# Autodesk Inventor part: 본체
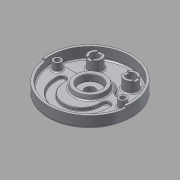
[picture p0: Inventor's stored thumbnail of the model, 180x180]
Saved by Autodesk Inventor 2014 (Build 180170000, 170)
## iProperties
Created: 2015-06
Part Number: 본체
Material: 알루미늄 6061
Document SubType Name: Modeling
Designer: MYHOME
Mass: 1070.54 g
Surface Area: 1035.57 cm^2
Volume: 395.033 cm^3
Density: 2.71 g/cm^3
Appearance: 알루미늄 - 평지
Author: MYHOME
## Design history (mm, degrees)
sketch "스케치1"
  geometry: C1 r 95 at (0, 0); 1 further point
  constraints: 1 centre point, 1 coincident
  dimensions: "d0" = 190 diameter of C1
extrude "돌출1" new body sketch "스케치1" distance "d1" = 32; taper "d2" = 0 deg
sketch "스케치3"
  geometry: L1 (-34.013, 24.639)-(-125.605, 24.639); L2 (34.013, 24.639)-(121.919, 24.639); C1 r 95 at (0, 0) reference; C2 r 90 at (0, 0); A1 r 42 centre (0, 0) between (-34.013, 24.639) and (34.013, 24.639)
  constraints: 4 end point, 2 centre point, 2 coincident, 2 point on circle, 1 collinear, 1 horizontal, 1 point on line
  dimensions: "d6" = 180 diameter of C2; "d125" = 84 diameter of A1; "d126" = 24.63947 distance from line of C1.centre L1
extrude "돌출3" cut sketch "스케치3" distance "d7" = 25; taper "d8" = 0 deg
sketch "스케치5"
  geometry: L1 (0, 0)-(-95, 0); L2 (0, 0)-(95, 0); L3 (0, 0)-(-94.075, -13.221); L4 (0, 0)-(94.075, -13.221); A1 r 95 centre (0, 0) between (-95, 0) and (95, 0) reference
  constraints: 8 end point, 4 point on circle, 1 collinear, 1 horizontal
  dimensions: "d12" = 8 deg angle of L3 L1; "d13" = 8 deg angle of L4 L2
extrude "돌출5" cut sketch "스케치5" distance "d14" = 5; taper "d15" = 0 deg
sketch "스케치11"
  geometry: L1 (-31.129, 16)-(-75.657, 16); L2 (31.129, 16)-(75.657, 16); A1 r 90 centre (0, 0) between (85.114, 29.25) and (-85.114, 29.25) reference; A2 r 35 centre (0, 0) between (31.129, 16) and (-31.129, 16); A3 r 10 centre (-75.657, 26) between (-85.114, 29.25) and (-75.657, 16); A4 r 10 centre (75.657, 26) between (75.657, 16) and (85.114, 29.25)
  constraints: 8 point on circle, 4 end point, 4 tangent, 3 centre point, 1 coincident, 1 collinear, 1 horizontal
  dimensions: "d36" = 70 diameter of A2; "d37" = 16 distance from line of A2.centre L1; "d38" = 16 distance from line of A1.centre L2; "d39" = 10 radius of A3; "d40" = 10 radius of A4
extrude "돌출13" join sketch "스케치11" distance "d56" = 7; taper "d57" = 0 deg
sketch "스케치14"
  geometry: C1 r 35 at (0, 0); A1 r 90 centre (0, 0) between (-85.114, 29.25) and (85.114, 29.25) reference
  constraints: 1 centre point, 1 coincident
  dimensions: "d58" = 70 diameter of C1
extrude "돌출14" join sketch "스케치14" distance "d59" = 10; taper "d60" = -10 deg
sketch "스케치15"
  geometry: L1 (75.657, 16)-(31.129, 16) reference; L2 (-50, -19)-(-50, -14); L3 (50, -19)-(50, -14); L4 (41, -14)-(41, -19); L5 (59, -14)-(59, -19); L6 (-59, -14)-(-59, -19); L7 (-41, -14)-(-41, -19); A1 r 35 centre (0, 0) between (-31.129, 16) and (31.129, 16) reference; A2 r 50 centre (0, -19) between (-50, -19) and (50, -19); A3 r 59 centre (0, -19) between (-59, -19) and (59, -19); A4 r 41 centre (0, -19) between (-41, -19) and (41, -19); A5 r 9 centre (-50, -19) between (-41, -19) and (-59, -19); A6 r 9 centre (50, -19) between (59, -19) and (41, -19); A7 r 9 centre (-50, -14) between (-59, -14) and (-41, -14); A8 r 9 centre (50, -14) between (41, -14) and (59, -14)
  constraints: 14 point on circle, 12 end point, 10 tangent, 7 centre point, 2 coincident, 2 horizontal alignment, 1 parallel, 1 perpendicular, 1 vertical alignment
  dimensions: "d61" = 19 distance of A1.centre A2.centre; "d62" = 41 radius of A4; "d63" = 59 radius of A3; "d85" = 5 distance of L2.start L2.end; "d86" = 5 distance of L3.start L3.end; "d87" = 18 diameter of A7; "d88" = 18 diameter of A8
sketch "스케치16"
  geometry: C1 r 15 at (-40, 52); C2 r 15 at (40, 52); A1 r 35 centre (0, 0) between (31.129, 16) and (-31.129, 16) reference
  constraints: 2 centre point, 1 horizontal alignment
  dimensions: "d64" = 30 diameter of C1; "d65" = 30 diameter of C2; "d66" = 52 vertical distance of A1.centre C2.centre; "d67" = 80 distance of C2.centre C1.centre; "d68" = 40 horizontal distance of A1.centre C1.centre
extrude "돌출15" join sketch "스케치16" distance "d69" = 25; taper "d70" = 0 deg
sketch "스케치17"
  geometry: C1 r 15 at (0, 0) reference; C2 r 15 at (80, 0) reference; C3 r 10 at (0, 0); C4 r 10 at (80, 0); 1 further point
  constraints: 2 centre point, 2 coincident
  dimensions: "d71" = 20 diameter of C3; "d72" = 20 diameter of C4
extrude "돌출16" cut sketch "스케치17" stored distance "d73" = 4.57143; taper "d74" = 0 deg
sketch "스케치18"
  geometry: L1 (6, -18.685)-(-6, -18.685); L2 (-6, -18.685)-(-6, 18.685); L3 (-6, 18.685)-(6, 18.685); L4 (6, 18.685)-(6, -18.685); L5 (6, -18.685)-(-6, 18.685); L6 (-6, -18.685)-(6, 18.685); C1 r 15 at (0, 0) reference; 1 further point
  constraints: 12 end point, 2 midpoint, 2 parallel, 1 horizontal, 1 perpendicular
  dimensions: "d76" = 12 distance of L2.end L3.end; "d77" = 37.37003 distance of L3.end L1.start
extrude "돌출17" cut sketch "스케치18" distance "d78" = 3; taper "d79" = 0 deg
sketch "스케치19"
  geometry: L1 (-22.578, 6)-(22.578, 6); L2 (22.578, 6)-(22.578, -6); L3 (22.578, -6)-(-22.578, -6); L4 (-22.578, -6)-(-22.578, 6); L5 (-22.578, 6)-(22.578, -6); L6 (22.578, 6)-(-22.578, -6); C1 r 10 at (0, 0) reference; 3 further points
  constraints: 12 end point, 3 midpoint, 2 parallel, 1 coincident, 1 horizontal, 1 perpendicular
  dimensions: "d81" = 12 distance between parallel lines of L3 L1; "d82" = 45.1561 distance of L1.start L1.end
extrude "돌출18" cut sketch "스케치19" distance "d83" = 3; taper "d84" = 0 deg
extrude "돌출19" cut sketch "스케치15" distance "d89" = 7; taper "d90" = 0 deg
sketch "스케치20"
  geometry: C1 r 33.237 at (0, 0) reference; C2 r 25 at (0, 0)
  constraints: 1 centre point, 1 coincident
  dimensions: "d91" = 50 diameter of C2
extrude "돌출20" cut sketch "스케치20" distance "d92" = 15; taper "d93" = 0 deg
sketch "스케치21"
  geometry: C1 r 95 at (0, 0) reference; C2 r 26 at (0, 0)
  constraints: 1 centre point, 1 coincident
  dimensions: "d94" = 52 diameter of C2
extrude "돌출21" join sketch "스케치21" distance "d95" = 12; taper "d96" = -15 deg
sketch "스케치22"
  geometry: C1 r 22.785 at (0, 0) reference; C2 r 11.5 at (0, 0)
  constraints: 1 centre point, 1 coincident
  dimensions: "d97" = 23 diameter of C2
extrude "돌출22" cut sketch "스케치22" stored distance "d98" = 12; taper "d99" = 0 deg
sketch "스케치24"
  geometry: L1 (75.657, 16)-(31.129, 16) reference; L2 (0, 0)-(74, 0); C1 r 9 at (-74, 0); C2 r 9 at (74, 0); A1 r 90 centre (0, 0) between (-85.114, 29.25) and (85.114, 29.25) reference; A2 r 74 centre (0, 0) between (-74, 0) and (74, 0)
  constraints: 3 centre point, 2 coincident, 2 end point, 2 horizontal alignment, 2 point on circle, 1 parallel
  dimensions: "d101" = 148 diameter of A2; "d102" = 18 diameter of C1; "d103" = 18 diameter of C2
extrude "돌출23" join sketch "스케치24" distance "d104" = 18; taper "d105" = 0 deg
sketch "스케치25"
  geometry: C1 r 26 at (0, 0) reference; C2 r 95 at (0, 0) reference; C3 r 9 at (-74, 0); C4 r 9 at (74, 0); A1 r 74 centre (0, 0) between (-74, 0) and (74, 0)
  constraints: 3 centre point, 3 coincident, 2 horizontal alignment, 2 point on circle
  dimensions: "d106" = 148 diameter of A1; "d107" = 18 diameter of C3; "d108" = 18 diameter of C4
extrude "돌출24" cut sketch "스케치25" distance "d109" = 11; taper "d110" = 0 deg
sketch "스케치26"
  geometry: C1 r 9 at (0, 0) reference; C2 r 9 at (-148, 0) reference; C3 r 5.5 at (0, 0); C4 r 5.5 at (-148, 0); 1 further point
  constraints: 2 centre point, 2 coincident
  dimensions: "d111" = 11 diameter of C3; "d112" = 11 diameter of C4
extrude "돌출25" cut sketch "스케치26" stored distance "d113" = 11; taper "d114" = 0 deg
sketch "스케치27"
  geometry: C1 r 95 at (0, 0) reference; C2 r 68 at (0, 0)
  constraints: 1 centre point, 1 coincident, 1 other
  dimensions: "d115" = 136 diameter of C2
feature "엠보싱1" sketch "스케치27" dims "d2" = 0, "d116" = 0.5, "d117" = 0
chamfer "모따기1" distance "d118" = 1; stored, may be unused: second distance "d119" = 2, angle "d120" = 45 deg
chamfer "모따기2" distance "d121" = 1; stored, may be unused: second distance "d122" = 2, angle "d123" = 45 deg
sketch "스케치29"
  geometry: L1 (-75.657, 16)-(-31.129, 16) reference; L2 (31.129, 16)-(75.657, 16) reference; A1 r 35 centre (0, 0) between (31.129, 16) and (-31.129, 16) reference; A2 r 90 centre (0, 0) between (85.114, 29.25) and (-85.114, 29.25) reference; A3 r 42 centre (0, 0) between (38.833, 16) and (-38.833, 16)
  constraints: 2 point on circle, 2 point on line, 1 centre point, 1 coincident
  dimensions: "d128" = 84 diameter of A3
extrude "돌출26" join sketch "스케치29" distance "d129" = 7; taper "d130" = 0 deg
fillet "모깎기2" dims "d131" = 10
fillet "모깎기4" dims "d133" = 3
fillet "모깎기5" dims "d134" = 0.3
fillet "모깎기6" dims "d135" = 3
fillet "모깎기7" dims "d136" = 5
fillet "모깎기8" dims "d137" = 1
fillet "모깎기9" dims "d138" = 3
node "솔리드1"
node "투영된 루프1"
node "투영된 루프2"
